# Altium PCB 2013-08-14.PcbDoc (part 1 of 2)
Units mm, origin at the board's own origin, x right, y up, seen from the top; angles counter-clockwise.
Board outline 30.96 x 91.67 mm, 2 copper layers (Top Layer, Bottom Layer); 88 components, 66 nets, 245 pads, 39 vias.
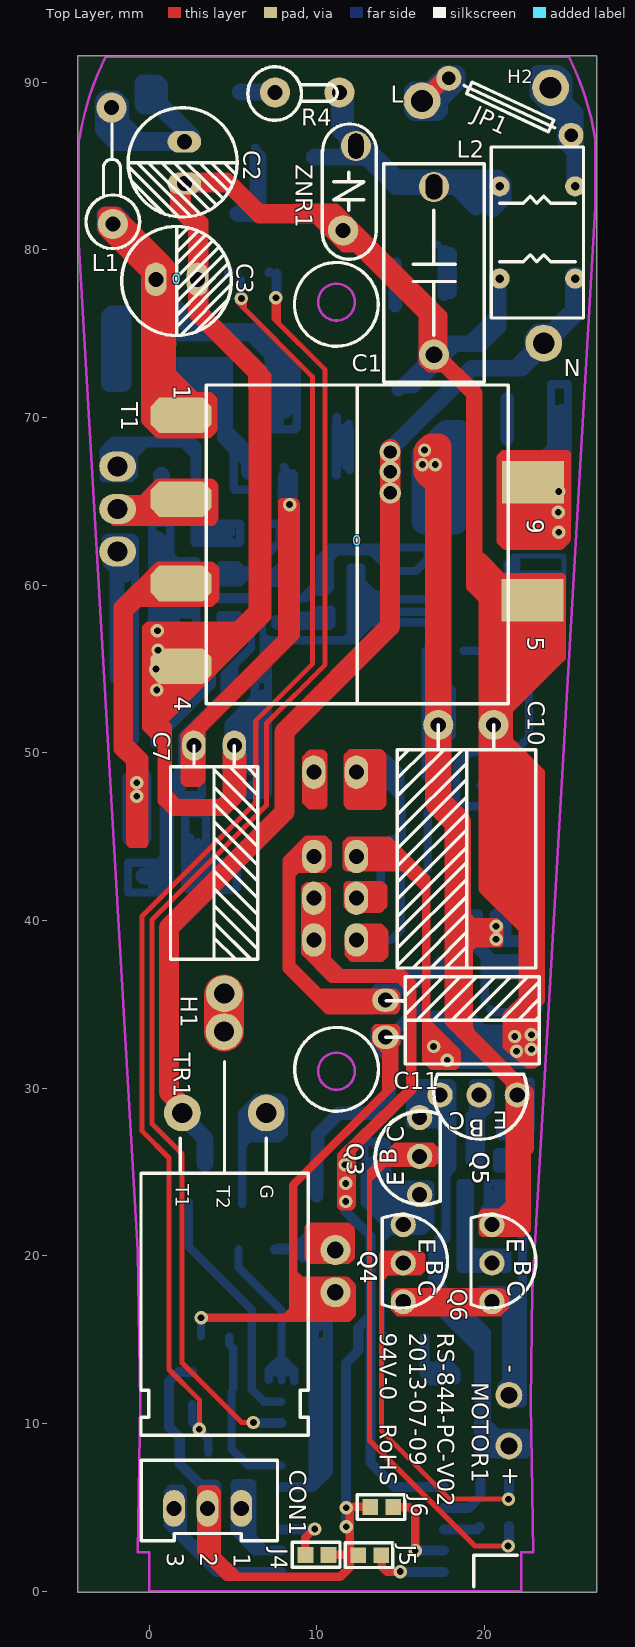
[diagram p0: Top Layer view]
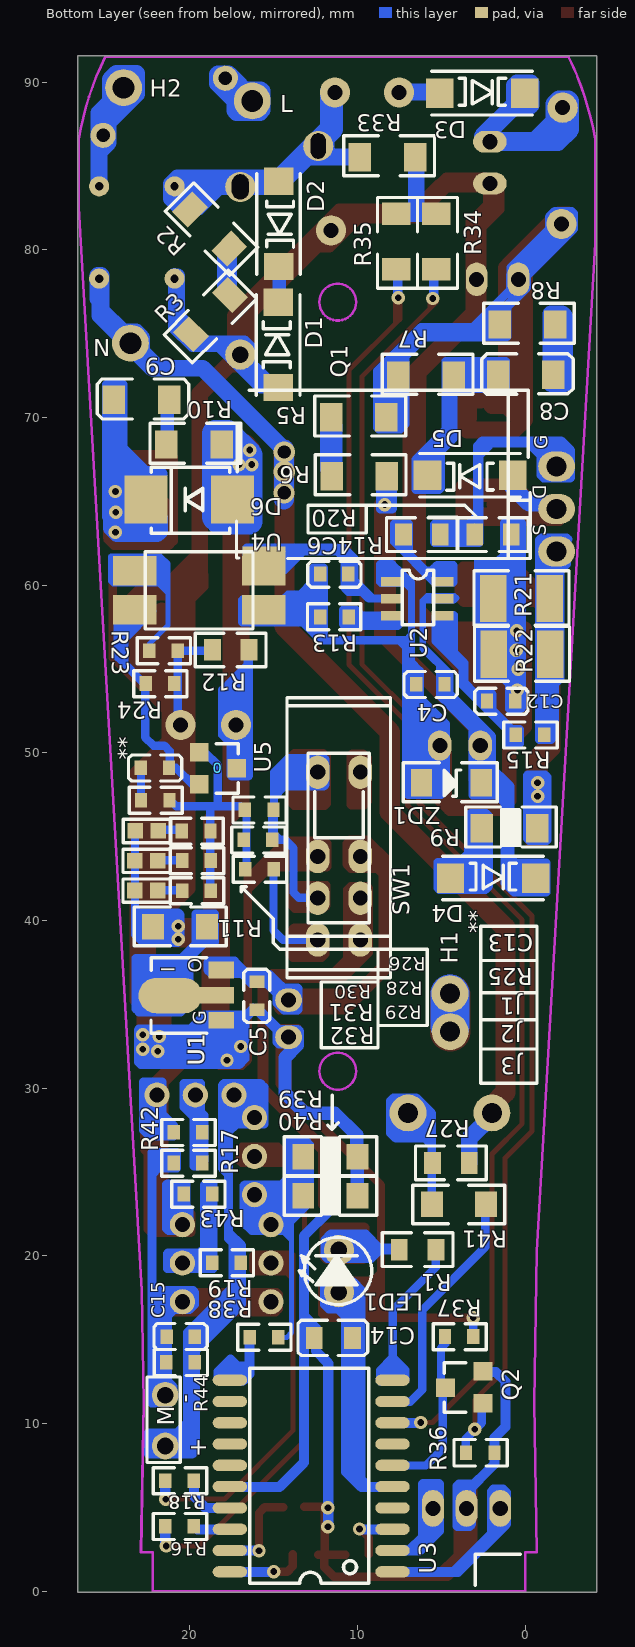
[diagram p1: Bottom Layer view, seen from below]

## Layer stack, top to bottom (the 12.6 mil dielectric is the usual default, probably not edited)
Top Layer: signal copper 0.0356
Dielectric: core 0.32, FR-4, Dk 4.8
Bottom Layer: signal copper 0.0356

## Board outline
-4.266,-0.075 26.694,-0.075 26.694,91.591 -4.266,91.591

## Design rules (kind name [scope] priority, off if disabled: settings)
Clearance [All] p1: gap=0.254
ComponentClearance [All] p1: gap=0.254 collisioncheckmode=3 verticalgap=0.254
PasteMaskExpansion PasteMaskExpansion_80 [HasPad('Free-201')] p1: expansion=-0.649
PasteMaskExpansion PasteMaskExpansion_78 [HasPad('Free-203')] p2: expansion=-0.623
PasteMaskExpansion [All] p3: expansion=-0.439
PolygonConnect [All] p1: connectstyle=Relief reliefconductorwidth=0.254 reliefentries=4 polygonreliefangle="90 Angle"
RoutingVias [All] p1: holewidth=0.711 width=1.27 viastyle="Through Hole" minholewidth=0.711 minwidth=1.27 maxholewidth=0.711 maxwidth=1.27
SolderMaskExpansion [(IsVia)] p1: expansion=-10
TestPointUsage [All] p1: valid=0 allowmultiple=FALSE
Testpoint [All] p1: side=15 testpointundercomponent=TRUE minsize=1.016 maxsize=2.54 preferedsize=1.524 minholesize=0 maxholesize=1.016 preferedholesize=0.813 testpointgrid=0.025 style=1023 order=0123456789
Width [All] p1: maxlimit=5 minlimit=2539.975 preferedwidth=2539.975 toplayer_minwidth=0 bottomlayer_minwidth=0
17 further rules are at their usual default settings.

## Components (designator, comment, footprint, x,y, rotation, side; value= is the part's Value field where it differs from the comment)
0 "Comment" 2.2uF/400V 1.646,78.247 r90 top
0 "Comment" TT1 12.405,62.655 r0 top locked
0 "Comment" TL431 18.324,49.085 r270 bottom
C4 "Comment" C0603 5.649,54.089 r180 bottom locked
C5 "" C0603 15.987,35.521 r270 bottom
C6 "Comment" C0603 11.389,60.667 r180 bottom
C7 "" c1 3.882,50.434 r0 top
C8 "Comment" C1206 -0.041,72.554 r0 top locked
C9 "Comment" C1206 22.881,71.058 r0 top
C10 "" C2 18.897,51.67 r180 top locked
C11 "" C3 14.107,34.15 r90 top
C12 "Comment" C0603 1.432,53.089 r180 bottom
C13 "Comment" C0603 22.083,49.11 r180 bottom
C14 "" C0805 11.44,15.1 r180 bottom
C15 "" C0603 20.533,15.176 r0 bottom
CON1 "" 3P 3.49,4.94 r0 top locked
D1 "Comment" D1 14.727,74.335 r270 top
D2 "Comment" D1 14.702,81.549 r90 top
D3 "Comment" D1 2.561,89.346 r0 top
D4 "Comment" D1 1.915,42.532 r0 top
D5 "Comment" D1 3.287,66.56 r180 top locked
D6 "Comment" D2 20.025,65.112 r0 bottom locked
J1 "Comment" R-J 22.565,45.351 r180 bottom
J2 "Comment" R-J 22.591,43.573 r180 bottom
J3 "Comment" R-J 22.591,41.795 r180 bottom
J4 "" RJJ 10.018,2.171 r0 top
J5 "" RJJ 13.167,2.146 r0 top
J6 "" RJJ 13.879,5.016 r0 top
JP1 "" FUSET 17.877,90.235 r335 top
L1 "Comment" L1 -2.164,81.549 r180 top
L2 "Comment" 共模电感 23.16,81.041 r270 top
LED1 "" LED 11.11,19.087 r180 bottom locked
Q3 "" Q1 16.139,25.945 r270 top locked
Q4 "" Q1 15.161,19.56 r90 top
Q5 "" Q1 19.66,29.591 r0 top
Q6 "" Q1 20.444,19.56 r90 top
R1 "" R0805#1 6.411,20.357 r0 bottom
R2 "Comment" R1206 18.817,81.244 r45 top
R3 "Comment" R1206 18.766,76.138 r135 top
R4 "" R2W 7.514,89.397 r0 top
R5 "Comment" R1206 9.921,70.014 r0 top
R6 "Comment" R1206 9.896,66.509 r0 top locked
R7 "Comment" R1206 5.903,72.504 r0 top locked
R8 "Comment" R1206 -0.142,75.552 r0 top
R9 "Comment" R1206 0.93,45.503 r0 top
R10 "Comment" R1206 19.757,68.391 r0 top
R11 "" R1 20.584,39.636 r0 bottom
R12 "Comment" R0805#2 17.561,56.146 r180 top locked
R13 "Comment" R0603 11.364,58.102 r0 bottom locked
R14 "Comment" R0805#2 6.157,63.029 r180 top
R15 "Comment" R0603 -0.295,51.082 r180 bottom
R16 "" R0603 20.61,3.873 r180 bottom
R17 "" R0603 20.102,25.539 r180 bottom
R18 "" R0603 20.61,6.591 r180 bottom
R19 "" R0603 17.816,19.595 r180 bottom
R20 "Comment" R0805#2 1.915,63.029 r180 top
R21 "Comment" R1210 0.213,59.21 r180 bottom
R22 "Comment" R1210 0.188,55.883 r180 bottom
R23 "Comment" R0603 21.575,56.095 r180 bottom locked
R24 "Comment" R0603 21.778,54.139 r180 bottom
R25 "Comment" R0603 22.057,47.18 r180 bottom
R26 "Comment" R0603 15.862,46.609 r180 bottom
R27 "" R0805#1 4.43,25.539 r0 bottom
R28 "Comment" R0603 15.936,44.818 r180 bottom
R29 "Comment" R0603 15.847,43.065 r180 bottom
R30 "Comment" R0603 19.621,45.339 r180 bottom locked
R31 "Comment" R0603 19.596,43.586 r180 bottom locked
R32 "Comment" R0603 19.596,41.783 r180 bottom locked
R33 "Comment" R1206 8.2,85.536 r0 top
R34 "Comment" R1206 5.304,80.507 r90 top
R35 "Comment" R1206 7.692,80.507 r90 top
R38 "" R0603 15.58,15.15 r180 bottom
R39 "" R1 11.618,25.92 r0 bottom
R40 "" R1 11.618,23.583 r0 bottom
R41 "" R1 3.947,23.075 r180 bottom
R42 "" R0603 20.102,27.368 r180 bottom
R43 "" R0603 19.517,23.685 r180 bottom
R44 "" R0603 20.559,13.652 r180 bottom
SW1 "" SW 11.1,43.847 r180 bottom locked
TR1 "" MSD 1.981,28.524 r0 top locked
U1 "" MSD1 19.644,35.547 r90 bottom
U2 "Comment" S08 6.436,59.194 r180 bottom locked
U3 "" SOP20 12.761,6.87 r90 bottom locked
U4 "" 光耦 19.441,59.702 r180 bottom
ZD1 "Comment" Z1 4.404,48.221 r180 bottom locked
ZNR1 "Comment" 10D 11.959,83.682 r0 top
? "Comment" 0.1UF/300V 16.988,78.755 r0 top
? "Comment" 2.2uF/400V 2.104,85.206 r0 top

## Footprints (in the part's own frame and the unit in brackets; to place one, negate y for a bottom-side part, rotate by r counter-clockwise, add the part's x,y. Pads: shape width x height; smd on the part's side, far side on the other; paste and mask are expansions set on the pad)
0.1UF/300V [mm]
  round 1.8 hole 1 slot 1.5 at 90 deg paste-0.53: 1(0,5.004)
  round 1.8 hole 1 paste-0.53: 2(0,-5.004)
  silkscreen extent -3,-6.63 3,6.38
2.2uF/400V [mm]
  oval 2x1.3 hole 0.9 paste-0.464: 1(0,1.245) 2(0,-1.244)
  silkscreen extent -3.35,-3.25 3.15,3.27
3P [mm]
  oval 1.3x2.2 hole 0.9 paste-0.45: 1(2.007,0) 2(0,0) 3(-2.007,0)
  silkscreen extent -3.96,-1.93 4.17,2.87
10D [mm]
  round 1.8 hole 0.9 slot 1.5 at 90 deg paste-0.467: 1(0.381,2.515)
  round 1.8 hole 0.9 paste-0.467: 2(-0.381,-2.515)
  silkscreen extent -1.63,-4.24 1.6,3.83
c1 [mm]
  oval 1.4x1.8 hole 0.9 paste-0.471: 1(-1.206,0) 2(1.207,0)
  silkscreen extent -2.6,-12.75 2.6,-1.27
C2 [mm]
  round 1.8 hole 0.9 paste-0.512: 1(-1.651,0) 2(1.651,0)
  silkscreen extent -4.17,1.47 4.09,14.5
C3 [mm]
  oval 1.4x1.6 hole 0.9 paste-0.471: 1(-1.105,-0.001) 2(1.105,0)
  silkscreen extent -2.71,-9.17 2.5,-0.99
C0603 [mm]
  rect 0.736x0.878 smd: 1(-0.838,0) 2(0.838,0)
  silkscreen extent -1.57,-0.79 1.6,0.76
C0805 [mil]
  rect 39.34x51 smd paste-25.5: 1(-45,0) 2(45,0)
  silkscreen extent -83,-41 81,42
C1206 [mil]
  rect 52.8x66.69 smd far side paste-33.35: 1(-65,0) 2(65,0)
D1 [mm]
  rect 1.631x1.755 smd far side paste-0.877: 1(2.54,0) 2(-2.54,0)
D2 [mm]
  rect 2.563x2.877 smd paste-1.438: 1(-2.578,0) 2(2.578,0)
  silkscreen extent -2.4,-1.93 2.27,2.01
FUSET [mm]
  round 1.5 hole 0.8 paste-0.316: 1(0,0) 2(8.052,0)
  silkscreen extent 1,-0.38 6.98,0.38
L1 [mm]
  round 1.8 hole 0.9 paste-0.469: 1(0,0) 2(0.076,-6.934)
  silkscreen extent -1.6,-5.97 1.6,1.47
LED [mm]
  round 1.8 hole 1 paste-0.47: A(0,-1.257) K(0,1.257)
  silkscreen extent -2.36,-1.99 1.95,2.02
MSD [mm]
  round 2.2 hole 1.2 paste-0.623: G(5.004,0) T1(0,0)
  round 2.2 hole 1.2: T2(2.489,4.851)
  silkscreen extent -2.46,-19.23 7.52,3.05
MSD1 [mil]
  rect 39.12x59.51 smd paste-29.75: G(-59,-60) I(0,-60) I(0,-37) O(59,-60)
  oval 83.28x148.96 smd paste-74.48: I(-1,60)
  silkscreen extent -90,-25 88,105
Q1 [mm]
  round 1.5 hole 0.9 paste-0.432: B(0.013,0) C(-2.299,0) E(2.299,0)
  silkscreen extent -2.67,-2.64 2.9,1.24
R1 [mm]
  rect 1.305x1.52 smd paste-0.76: 1(-1.612,0) 2(1.613,0)
  silkscreen extent -2.76,-1.17 2.73,1.14
R2W [mm]
  round 1.8 hole 0.9 paste-0.469: 1(0,0) 2(3.835,0)
  silkscreen extent -1.62,-1.67 3.71,1.52
R0603 [mm]
  rect 0.736x0.878 smd: 1(0.851,0) 2(-0.851,0)
  silkscreen extent -1.56,-0.79 1.61,0.76
R0805#1 [mm]
  rect 0.999x1.295 smd paste-0.648: 1(-1.092,0) 2(1.092,0)
  silkscreen extent -2.11,-1.02 2.11,0.99
R0805#2 [mm]
  rect 0.999x1.295 smd far side paste-0.648: 1(-1.092,0) 2(1.092,0)
R1206 [mil]
  rect 52.8x66.69 smd far side paste-33.35: 1(-65,0) 2(65,0)
  Bottom Layer lines w19.68: -73.91,22.54 -70.95,19.58
R1210 [mm]
  rect 1.567x2.807 smd paste-1.403: 1(-1.689,0) 2(1.689,0)
  silkscreen extent -2.83,-1.6 2.83,1.65
R-J [mm]
  rect 0.939x0.939 smd paste-0.47: 1(-0.686,0) 2(0.686,0)
  silkscreen extent -1.4,-0.71 1.42,0.69
RJJ [mil]
  rect 36.97x36.97 smd paste-18.48: 1(-27,0) 2(27,0)
  silkscreen extent -58,-29 54,29
S08 [mm]
  rect 1.301x0.565 smd paste-0.65: 1(-1.511,1.004) 2(-1.511,0.012) 3(-1.511,-1.004) 4(1.512,-1.004) 5(1.512,0.012) 6(1.512,1.004)
  silkscreen extent -0.9,-1.56 0.98,1.69
SOP20 [mil]
  oval 26.31x80.65 smd paste-40.33: 1(-225,-191) 2(-175,-191) 3(-125,-191) 4(-75,-191) 5(-25,-191) 6(25,-191) 7(75,-191) 8(125,-191) 9(175,-191) 10(225,-191) 11(225,191) 12(175,191) 13(125,191) 14(75,191) 15(25,191) 16(-25,191) 17(-75,191) 18(-125,191) 19(-175,191) 20(-225,191)
  silkscreen extent -252,-135 253,144
SW [mm]
  oval 1.4x2 hole 0.9 paste-0.448: 1(1.27,5.004) 2(1.27,-0.025) 3(1.27,-2.515) 4(1.27,-5.004) 5(-1.27,-5.004) 6(-1.27,-2.514) 7(-1.27,-0.025) 8(-1.27,5.004)
  silkscreen extent -3.1,-7.26 3.07,9.45
TL431 [mil]
  rect 43.66x43.66 smd paste-21.85: 1(-37.5,-44) 2(37.5,-44) 3(0.49,44)
  silkscreen extent -58,-4 58,47
TT1 [mm]
  oct 3.655x2.126 smd paste-1.827: 1(-10.503,7.48) 3(-10.503,2.476) 4(-10.503,-7.48) 5(-10.503,-2.553)
  rect 3.699x2.537 smd paste-1.85: 7(10.452,-3.543) 9(10.503,3.492)
  silkscreen extent -9,-9.72 9,9.28
Z1 [mil]
  rect 50.28x64.72 smd paste-32.36: 1(-70,0) 2(70,0)
  silkscreen extent -113,-45 108,47
光耦 [mm]
  rect 2.585x1.748 smd paste-1.293: 1(-3.848,1.169) 2(-3.848,-1.168) 3(3.848,-1.168) 4(3.848,1.169)
  silkscreen extent -3.21,-2.31 3.21,2.29
共模电感 [mm]
  round 1.2 hole 0.5: 1(-2.75,2.25) 2(-2.75,-2.25) 3(2.75,-2.25) 4(2.75,2.25)
  silkscreen extent -5.1,-2.75 5.1,2.75

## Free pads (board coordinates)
  round 2.2 hole 1.2: 1(4.481,35.641)
  round 1.6 hole 1 paste-0.475: 1(21.463,8.661) 2(21.463,11.684)
  rect 2.585x1.748 smd far side paste-1.293: 4(15.57,61.443)
  rect 1.631x1.755 smd far side paste-0.877: 32(5.817,66.573) 33(0.737,66.573)
  rect 0.999x1.295 smd far side paste-0.648: 50(12.573,15.088) 51(10.287,15.088)
  rect 1.109x1.109 smd far side paste-0.555: 89(4.75,12.141) 90(2.515,13.106) 91(2.515,11.201)
  rect 0.736x0.878 smd far side: 138(4.775,15.189) 139(3.099,15.189) 140(3.531,8.255) 141(1.829,8.255)
  rect 0.939x0.939 smd paste-0.47: 174(10.693,2.159) 175(9.322,2.159)
  round 2.2 hole 1.3: 201(16.277,88.889) 201(23.541,74.437) 201(23.948,89.677)
  oval 2.2x1.8 hole 1.2 paste-0.588: 250(-1.88,62.008) 251(-1.88,64.548) 252(-1.88,67.088)

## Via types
v1: diameter 0.8, hole 0.4, Top Layer to Bottom Layer, 36 vias
v2: diameter 1.27, hole 0.8, Top Layer to Bottom Layer, 3 vias

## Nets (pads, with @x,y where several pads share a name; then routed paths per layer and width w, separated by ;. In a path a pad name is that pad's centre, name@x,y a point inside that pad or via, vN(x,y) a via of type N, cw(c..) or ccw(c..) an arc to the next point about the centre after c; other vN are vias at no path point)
H2: JP1.2 L2.1 pad.201@23.948,89.677 | length 20.3
  Bottom Layer w1: pad.201@23.186,89.499 23.186,89.296 24.684,87.797 ; pad.201@23.871,89.702 25.41,88.163 L2.1@25.41,83.791 ; 24.938,88.33 24.74,88.529 24.74,90.18 24.379,90.54 23.211,90.54 23.186,90.515 23.186,89.321 23.516,88.991 23.744,88.991 24.862,87.873 24.862,86.4 25.41,85.852 L2.1@25.41,83.835
L: ?.1@16.988,83.759 D2.1 L2.2 R2.2 R4.2 R33.2 ZNR1.1 | length 41.3
  Bottom Layer w0.3: D2.1@14.984,83.756 L2.2@20.821,83.756
  Bottom Layer w1: R33.2@9.851,85.536 ZNR1.1@12.899,85.536 ; 11.222,85.536 11.502,85.536 ZNR1.1@11.806,85.841 ; R4.2@11.349,89.397 11.349,87.162 14.727,83.784 L2.2@20.95,83.784 ; R4.2@11.73,89.448 11.73,87.314 14.753,84.292 20.747,84.292 21.103,83.936 21.103,83.073 R2.2@20.468,82.438 ; ZNR1.1@11.857,86.654 11.857,85.892 ZNR1.1@11.908,85.841 ; 18.385,83.682 R2.2@19.503,82.565 ; 19.452,83.2 19.706,83.454 ; R2.2@20.011,82.996 20.442,83.428 L2.2@20.874,83.428
L-IN: JP1.1 pad.201@16.277,88.889 | length 11.5
  Top Layer w1: pad.201@16.277,88.889 JP1.1@17.623,90.235
  Bottom Layer w1: pad.201@16.251,88.788 16.251,89.067 17.674,90.489 18.334,90.489 18.36,90.464 18.36,89.931 17.318,88.889 17.318,88.305 17.217,88.203 15.82,88.203 15.693,88.33 15.693,89.473 15.769,89.55 pad.201@16.861,89.55
N: 0.2@2.891,78.247 0.4 0.7 ?.2 C4.1 C5.2 C6.1 C7.2 C10.1 C11.1 C12.2 C14.2 D1.1 L2.3 LED1.A pad.51 pad.139 R3.1 R12.1 R13.1 R20.2 R21.1 R22.1 R23.1 R24.1 R39.1 R40.1 SW1.7 U1.G U2.1 U3.5 U4.3 ZD1.1 ZNR1.2 | length 806.1
  Top Layer w0.5: 1.128,51.595 1.128,47.548 1.668,47.008 4.245,47.008 4.624,47.387 4.624,49.982 4.732,50.09 5.383,50.09 5.561,49.912 5.561,47.518 4.518,46.475 1.412,46.475 0.761,47.126 0.761,50.563 -0.164,51.488 -0.164,57.474 -0.046,57.592 5.205,57.592 6.165,58.552 6.165,71.933 ; ?.2@1.494,84.114 1.494,82.387 2.561,81.32 2.561,76.138 6.142,72.557 6.142,71.77 ; 2.256,82.742 3.297,81.701 3.297,76.265 7.054,72.509 7.054,58.102 6.828,57.876 ; v1@3.238,16.314 11.877,16.314 12.097,16.534 12.097,18.193 11.759,18.531 9.05,18.531 8.595,18.986 ; 8.151,16.314 8.595,16.758 8.595,24.218 14.641,30.263 C11.1@14.641,32.81 ; 14.148,29.746 C11.1@14.148,32.48 ; 14.321,31.841 14.321,32.019 13.559,32.781 13.559,33.568 14.702,33.568 14.753,33.517 14.753,32.73 14.346,32.323 14.346,31.663 ; C11.1@14.367,33.064 C11.1@14.61,32.821 ; 14.437,30.06 C11.1@14.437,32.88 ; 14.437,30.88 14.539,30.981 ; 16.542,33.944 18.358,32.128 18.358,31.474 18.227,31.343 ; 16.542,41.858 15.22,43.18 11.83,43.18 11.795,43.215 11.795,44.602 11.949,44.756 14.296,44.756 16.542,42.51 ; 16.542,42.532 16.542,31.686 16.885,31.343 18.195,31.343 ; 19.147,60.619 19.147,59.899 19.902,59.144 19.902,41.855 22.272,39.485 22.272,35.926 ; 19.842,61.705 21.075,60.472 24.607,60.472 24.607,55.683 21.442,52.518 21.442,50.766 23.351,48.857 23.351,35.215 22.942,34.806 ; 21.585,34.381 21.585,32.679 21.636,32.628 ; v1@21.89,32.273 21.89,34.736 ; 22.449,35.473 21.331,34.355 21.331,32.508 22.582,31.435 22.819,31.435 22.942,31.432 22.942,36.806
  Top Layer w0.8: ?.2@2.027,83.86 5.075,83.86 6.599,82.336 10.587,82.336 16.937,75.986 16.937,73.802 ?.2@16.988,73.751 ; ?.2@2.104,83.962 2.104,82.59 2.916,81.777 2.916,76.519 6.65,72.786 6.65,71.795 ; ?.2@2.383,84.216 4.669,84.216 5.863,83.022 ; ?.2@2.459,83.835 4.694,83.835 6.549,81.98 9.952,81.98 11.679,80.253 12.365,80.253 16.48,76.138 16.48,73.37 16.759,73.09 17.648,73.09 ; 8.784,82.361 11.095,82.361 17.394,76.062 ?.2@17.394,73.548
  Top Layer w1: 0.216,51.559 0.216,56.941 0.428,57.153 4.979,57.153 0.5,52.674 0.5,53.539 3.451,56.49 2.053,56.49 0.168,54.605 0.168,55.612 1.093,56.537 ; 0.642,51.15 0.642,52.045 6.722,58.125 6.722,71.862 ; 1.063,47.275 1.608,46.73 4.435,46.73 5.11,47.405 C7.2@5.11,49.604 ; 9.027,18.258 9.027,16.794 9.039,16.806 11.457,16.806 11.51,16.859 11.51,17.992 11.474,17.956 9.407,17.956 ; 9.43,17.428 LED1.A@10.569,17.428 ; SW1.7@12.257,44.306 14.26,44.306 14.936,43.63 SW1.7@12.612,43.63 ; ?.2@17.064,73.776 19.401,71.439 19.401,60.39 ; ?.2@17.181,73.748 ?.2@17.206,73.748 ; 17.235,31.882 16.844,32.273 16.844,32.973 17.839,31.978 v1@17.839,31.799 ; 19.487,60.424 20.34,59.571 20.34,42.007 22.711,39.636 22.711,39.494 ; 19.57,61.337 21.312,59.595 22.876,59.595 24.085,58.386 24.085,55.825 21.028,52.768 21.028,50.634 22.77,48.892 22.77,35.607 22.533,35.37 ; 20.992,59.547 20.992,42.421 22.308,41.105 22.308,48.975 21.62,49.663 21.62,41.865 ; 0.7@21.668,58.481 21.668,53.859 23.54,55.731 23.54,57.983 23.184,57.627 22.189,57.627 22.379,57.437 22.379,54.83 23.114,55.565 23.114,57.818 ; v1@22.533,32.048 22.533,37.37
  Bottom Layer w0.4: 6.815,59.779 7.478,60.442 U2.1@8.027,60.442 ; 6.858,54.788 6.772,54.874 6.772,60.178 7.429,60.835 8.696,60.835 ; 7.127,60.204 7.17,60.204 7.521,60.555 8.566,60.555 ; 7.133,60.097 8.61,60.097 8.696,60.183 8.696,61.043 ; 7.747,60.879 7.844,60.879
  Bottom Layer w0.5: v1@0.185,53.678 v1@0.714,53.678 ; 0.811,54.993 1.35,55.532 2.741,55.532 2.805,55.596 ; 0.961,54.218 0.961,54.98 ; 1.062,60.873 2.612,60.873 ; 1.088,61.508 1.469,61.127 2.612,61.127 ; 1.545,57.596 2.688,57.596 ; 1.621,57.342 2.637,57.342 ; pad.139@3.099,15.189 v1@3.099,16.169 ; 5.397,47.992 5.397,51.662 5.882,52.147 5.882,49.098 6.109,48.871 6.109,52.643 5.042,51.576 5.042,47.932 5.203,47.771 5.818,47.771 6.405,48.358 6.405,53.182 6.761,53.538 ZD1.1@6.761,47.717 ; C4.1@6.691,54.4 6.691,55.052 ; 6.838,60.066 6.838,60.293 ; 6.96,47.501 5.015,47.501 4.74,47.776 4.74,51.743 6.292,53.295 6.292,54.895 6.831,55.434 6.831,56.933 7.057,56.707 12.172,56.707 13.265,57.8 U4.3@16.785,57.8 ; 6.982,47.501 7.095,47.614 7.095,56.303 7.499,56.707 ; 7.405,60.724 7.928,61.246 8.641,61.246 8.641,60.781 ; 11.724,56.739 12.021,57.036 12.021,61.035 12.646,61.035 12.646,60.167 12.985,59.828 ; 12.463,57.289 C6.1@12.463,60.398 ; 12.609,58.232 12.9,58.523 13.234,58.523 ; 12.645,59.832 12.924,59.552 12.924,59.273 ; 12.646,60.211 13.432,59.425 14.143,59.425 14.397,59.171 16.81,59.171 16.861,59.12 U4.3@16.861,57.8 ; 12.652,58.771 14.258,58.771 ; 12.695,59.288 14.253,59.288 ; 12.706,58.97 U4.3@14.42,58.97 ; 12.733,57.268 12.733,57.99 13.158,58.415 U4.3@16.759,58.415 ; 12.942,59.369 13.903,59.369 ; 12.949,57.825 13.178,58.054 U4.3@14.753,58.054 ; C11.1@13.559,33.339 C11.1@13.737,33.517 ; C11.1@13.584,33.517 14.677,33.517 15.843,34.683 C5.2@15.987,34.683 ; C11.1@14.296,32.628 14.702,32.628 14.804,32.73 C11.1@14.804,33.339 ; 14.854,33.492 15.921,34.559 C5.2@15.972,34.559 ; D1.1@14.88,71.744 D1.1@14.982,71.744 ; C5.2@16.061,34.774 16.699,34.136 16.699,31.742 17.044,31.397 22.919,31.397 23.07,31.548 23.07,33.488 ; C5.2@16.213,34.8 16.641,34.372 19.146,34.372 19.976,33.542 23.048,33.542 ; R12.1@18.758,56.103 20.612,56.103 20.709,56.006 C10.1@20.709,51.551 ; 0.185,52.682 0.249,52.618 0.935,52.618 0.961,52.643 0.961,54.117 1.291,54.447 2.764,54.447 2.805,54.488 2.805,61.439 1.608,61.439 1.263,61.784 1.263,63.725 0.185,63.725 0.185,52.682
  Bottom Layer w0.6: U3.5@7.899,6.223 9.769,6.223 10.668,7.122 10.668,16.387 11.148,16.867 11.698,16.867 11.924,17.093 11.924,18.311 ; 9.387,6.223 10.34,7.176 pad.51@10.34,14.862 ; 9.822,6.658 9.822,17.966 10.253,18.397 11.827,18.397 ; 10.194,15.806 10.194,17.552 10.593,17.951 LED1.A@10.593,18.01 ; 10.194,16.597 11.331,17.734 LED1.A@11.331,18.133 ; LED1.A@10.453,17.379 LED1.A@10.453,17.605
  Bottom Layer w0.8: R40.1@10.006,23.583 R39.1@10.006,25.882 ; R39.1@10.054,25.872 10.054,27.218 11.349,28.513 13.127,28.513 14.321,29.707 14.321,31.815 13.584,32.552 C11.1@13.584,33.361 ; C11.1@13.828,33.057 C11.1@14.183,33.083 ; D1.1@14.854,71.643 17.521,74.31 19.833,74.31 20.91,75.387 20.91,78.515 20.895,78.501 20.722,78.501 20.696,78.475 20.696,76.062 19.122,74.487 16.759,74.487 16.404,74.132 ?.2@16.404,73.319 ; D1.1@15.286,71.846 15.769,71.846 18.309,74.386 18.334,74.386
  Bottom Layer w1: v1@0.58,53.532 0.498,53.614 0.498,62.721 0.649,62.57 0.649,59.358 1.489,58.518 R21.1@2.504,58.518 ; 0.628,55.5 1.317,56.189 R21.1@1.317,58.776 ; C11.1@14.11,33.009 C11.1@14.346,33.009 ; 17.238,33.488 17.238,32.109 17.573,31.774 22.37,31.774 22.499,31.903 22.499,32.324 22.467,32.356 18.413,32.356 17.874,32.895 ; 17.239,33.844 18.909,33.844 19.653,33.1 v1@22.736,33.1 ; 17.874,32.443 17.874,33.057 17.906,33.025 19.2,33.025
  other v1: 3.099,16.307 17.78,31.674 21.916,32.196 22.805,32.323 16.967,32.487 21.814,33.085 22.805,33.187 0.457,53.753 0.406,54.998 0.533,56.115 0.498,57.28
N-IN: L2.4 pad.201@23.541,74.437 R27.1 TR1.T1 | length 79.7
  Top Layer w1: TR1.T1@1.941,28.46 TR1.T1@1.941,28.993 ; v2@14.361,67.949 v2@14.372,67.96
  Top Layer w1.2: TR1.T1@1.941,28.994 1.18,29.754 1.18,39.579 8.073,46.471 8.073,51.255 14.361,57.543 v2@14.361,67.949 ; v2@14.397,65.674 v2@14.397,68.112
  Bottom Layer w1: TR1.T1@1.941,28.384 3.338,26.987 R27.1@3.338,25.539 ; v2@14.372,68.087 19.223,72.938 22.22,72.938 25.37,76.088 L2.4@25.37,78.374 ; 22.017,73.065 22.881,73.929 22.881,74.767 23.211,75.097 23.998,75.097 25.294,76.392 25.294,78.475 25.497,78.475 25.472,78.45 25.472,77.098 25.37,76.996
  Bottom Layer w1.2: v2@14.372,65.126 v2@14.372,68.087
  other v2: 14.376,65.507 14.372,66.777 14.372,67.945
NewNet1: 
NewNet2: J4.1 pad.175 U3.3 | length 3.5
  Top Layer w0.5: pad.175@9.318,2.187 9.318,3.195 v1@9.839,3.716
  Bottom Layer w0.6: U3.3@7.899,3.683 v1@9.662,3.683
  other v1: 9.881,3.708
NewNet3: J5.2 U3.20 | length 4.4
  Top Layer w0.5: J5.2@13.869,2.211 13.869,1.476 14.189,1.156 v1@14.936,1.156
  Bottom Layer w0.6: v1@15.106,1.143 U3.20@17.602,1.143
  other v1: 14.986,1.168
NewNet4: J6.2 U3.19 | length 5.5
  Top Layer w0.5: J6.2@14.42,5.008 15.528,5.008 15.875,4.661 v1(15.875,2.413)
  Bottom Layer w0.6: v1@15.966,2.413 U3.19@17.602,2.413
NewNet5: C14.1 CON1.2 J4.2 J5.1 J6.1 pad.50 pad.90 pad.141 pad.174 SW1.3 SW1.4 U3.16 | length 154.1
  Top Layer w0.5: 3.629,2.365 3.629,5.191 3.481,5.339 3.481,2.181 4.601,1.061 4.832,1.061 ; 5.152,1.008 4.032,2.128 4.032,5.938 3.89,6.08 3.125,6.08 3.096,6.051 3.096,2.37 4.607,0.859 11.403,0.859 11.973,1.429 11.973,2.092 ; 10.526,37.788 11.748,36.566 12.031,36.849 ; 10.551,36.849 15.079,36.849 15.566,36.362 15.566,30.037 ; 10.598,37.301 10.598,41.853 10.397,42.054 9.443,42.054 9.318,41.929 9.318,38.082 10.881,36.518 14.939,36.518 15.684,35.773 ; 10.678,37.204 10.831,37.052 10.907,37.052 ; pad.174@10.716,2.169 J5.1@12.334,2.169 ; v1@11.831,23.118 11.831,25.918 ; 11.961,2.371 11.961,4.926 11.858,5.029 J6.1@13.183,5.029 ; 14.802,36.849 15.706,35.944 ; 15.108,36.845 15.706,36.247 15.706,29.903 12.103,26.3 12.103,23.047 12.019,22.963 11.476,22.963 11.451,22.988 11.451,25.973 15.581,30.002
  Top Layer w1: SW1.4@9.78,38.093 SW1.3@9.78,41.637 ; 10.165,37.781 SW1.3@10.165,41.432
  Bottom Layer w0.6: pad.90@2.546,13.073 1.749,13.073 1.177,12.501 1.177,9.807 1.829,9.155 1.829,7.581 3.538,5.872 CON1.2@3.538,5.376 ; v1(11.688,25.431) 11.688,22.697 13.201,21.184 13.201,7.662 14.64,6.223 U3.16@17.602,6.223 ; v1@11.741,3.889 11.741,13.59 12.474,14.323 12.474,15.698 13.201,16.425 ; CON1.2@3.215,3.996 3.312,3.899 4.023,3.899 4.023,6.271 3.948,6.346 3.215,6.346 CON1.2@3.215,3.996
  other v1: 11.76,3.835 11.76,4.978 11.724,23.242 11.724,24.32
NewNet6: 0.5 R9.1 | length 87.2
  Top Layer w0.5: -1.118,44.632 -1.118,49.432 -1.87,50.184 -1.87,58.748 0.559,61.177 3.711,61.177 3.949,60.939 3.949,59.222 3.67,58.943 -0.614,58.943 -1.224,58.333 -1.224,50.635 -0.271,49.682 -0.271,44.578 -1.106,44.578
  Top Layer w1: -0.768,44.851 -0.768,49.651 -1.574,50.457 -1.574,58.505 0.571,60.65 3.332,60.65 3.463,60.519 3.463,59.453 3.332,59.322 -0.495,59.322
  Bottom Layer w0.5: R9.1@-0.968,45.668 -0.968,48.385 -0.806,48.547 -0.806,46.219 -0.407,45.82 -0.407,48.45 ; -0.192,48.698 -1.183,48.698 -1.323,48.558 -1.323,44.795 -1.291,44.763 -0.235,44.763 -0.116,44.882 -0.116,48.66 -0.154,48.698
  other v1: -0.741,47.411 -0.741,48.224
NewNet7: D4.1 R9.2 | length 28.7
  Bottom Layer w0.5: R9.2@2.471,44.947 2.471,42.381 2.622,42.23 3.592,42.23 2.924,42.898 2.924,44.677 2.837,44.59 2.837,42.402 ; 2.934,41.831 5.112,41.831 5.22,41.939 5.22,43.491 3.894,43.491 3.398,43.987 3.398,46.251 3.247,46.402 2.331,46.402 2.158,46.229 2.158,42.036 2.363,41.831 D4.1@5.079,41.831 ; 3.118,43.793 3.71,43.201 3.71,42.543 3.204,43.049 3.204,44.052
NewNet8: C4.2 C7.1 D4.2 R6.1 U2.5 ZD1.2 | length 118.2
  Top Layer w0.5: 7.943,63.109 8.073,63.239 ; 8.614,56.87 8.614,56.893 8.758,57.038 8.758,64.861 8.657,64.962 7.946,64.962 7.943,64.96 7.943,56.857 2.124,51.038 2.124,48.318 2.237,48.205 2.923,48.205 3.113,48.395 3.113,51.369 8.69,56.946
  Top Layer w1: 2.621,48.62 C7.1@2.621,51.097 ; 8.2,62.676 8.2,63.112 ; 8.287,56.952 8.287,62.712 ; 8.454,63.21 v1@8.454,64.658
  Bottom Layer w0.4: 5.958,59.1 4.259,59.1 4.125,59.234 4.233,59.342 5.839,59.342 6.109,59.072 6.109,56.224
  Bottom Layer w0.5: 1.382,47.361 1.716,47.695 1.716,48.342 1.22,47.846 1.22,47.642 1.328,47.534 1.328,47.296 1.986,47.954 1.986,48.849 ; 1.977,48.986 1.977,50.992 4.519,53.535 4.519,54.701 6.028,56.21 ; 2.205,49.338 0.875,48.008 0.875,43.76 0.553,43.438 -1.259,43.438 -1.259,41.67 0.66,41.67 1.231,42.241 1.231,47.027 1.684,47.48 3.139,47.48 3.139,51.683 ; C7.1@2.406,51.177 2.406,49.054 2.719,48.741 2.719,51.609 4.799,53.689 C4.2@4.799,53.872 ; 3.139,51.469 5.075,53.405 5.075,55.107 ; 5.015,53.559 5.015,55.004 ; R6.1@7.895,65.775 7.895,64.556 7.92,64.531 8.022,64.531 ; 7.996,64.531 v1@8.628,64.531 ; v1@8.216,65.039 R6.1@8.216,65.896 ; v1@8.328,64.732 8.577,64.732 v1@8.642,64.797 ; R6.1@8.572,66.677 8.642,66.607 v1@8.642,64.531
  Bottom Layer w1: D4.2@-0.31,42.661 0.142,42.661 0.735,43.254 0.735,42.488 0.391,42.144 ; v1@8.189,64.871 R6.1@8.189,66.484
  other v1: 8.377,64.81
NewNet10: 
NewNet11: Q3.B R16.2 | length 45.3
  Top Layer w0.3: 13.146,24.516 14.088,25.458 16.957,25.458 17.122,25.623 17.122,26.389 16.909,26.602 14.698,26.602 13.146,25.05 13.146,8.99 19.444,2.692 v1(21.412,2.692)
  Top Layer w0.5: 14.586,26.005 14.377,26.005 13.322,24.95 13.322,25.045 14.107,25.83 15.249,25.83
  Top Layer w1: Q3.B@16.631,26.193 15.007,26.193 15.256,25.944 Q3.B@16.678,25.944
  Bottom Layer w0.6: v1@21.463,2.826 R16.2@21.463,3.886
NewNet12: Q4.B R18.2 | length 30.7
  Top Layer w0.3: 13.893,18.655 14.231,18.993 16.156,18.993 16.322,19.159 16.322,20.018 16.174,20.166 13.945,20.166 13.851,20.072 13.851,9.571 17.936,5.486 v1(21.438,5.486)
  Top Layer w1: 14.254,19.378 15.712,19.378 15.813,19.479 15.813,19.674 15.765,19.722 14.325,19.722 14.515,19.532 Q4.B@14.77,19.532
  Bottom Layer w0.6: v1@21.463,5.512 R18.2@21.463,6.579
NewNet13: R11.1 U1.I | length 32.7
  Bottom Layer w0.5: R11.1@19.34,38.925 19.594,38.671 19.594,38.569 ; U1.I@20.03,35.148 20.03,37.767 19.092,38.705 18.499,38.705 18.499,40.398 19.653,40.398 19.653,38.597 20.482,37.768 23.231,37.768 23.231,34.727 23.038,34.534 20.536,34.534 U1.I@20.353,34.717 ; 20.731,36.69 22.402,36.69 22.499,36.787 22.499,36.592 22.779,36.312 22.779,37.11 22.747,37.142 20.753,37.142 20.623,37.272 20.623,36.928 20.353,36.658 20.353,37.51 20.3,37.563 22.843,37.563 23.059,37.347 23.059,34.932 22.823,34.696 U1.I@22.477,34.696
NewNet14: C5.1 C11.2 SW1.2 U1.O | length 69.1
  Top Layer w0.5: 8.447,42.712 9.027,43.292 ; 8.672,43.148 8.494,42.97 8.494,37.354 10.116,35.731 10.094,35.579 ; 8.678,43.097 10.408,43.097 10.657,43.346 10.657,44.596 10.444,44.809 9.395,44.809 8.192,43.606 8.192,37.125 10.399,34.918 ; 9.684,35.63 13.778,35.63 C11.2@14.509,35.102 ; 10.124,35.702 14.626,35.702 14.753,35.524 14.753,34.813 14.677,34.686 13.153,34.686 ; 10.294,35.023 10.657,34.66 14.651,34.66 ; 10.5,34.969 13.269,34.969 13.32,35.02 ; 10.5,35.325 C11.2@13.396,35.325
  Top Layer w1: SW1.2@9.792,44.092 9.247,44.092 8.607,43.452 SW1.2@10.076,43.452
  Bottom Layer w0.5: C11.2@13.98,35.115 13.98,35.547 15.221,36.787 16.516,36.787 17.324,37.595 18.866,37.595 ; C11.2@14.321,35.371 14.321,35.473 15.464,36.616 C5.1@15.769,36.616 ; 14.421,35.987 13.565,35.987 13.534,35.956 13.534,34.686 13.559,34.66 14.397,34.66 14.804,35.067 14.804,35.625 15.415,36.237 16.333,36.237 16.926,36.83 18.725,36.83 18.931,37.036 18.931,37.52 ; 17.325,37.164 U1.O@18.521,37.164
NewNet15: Q3.E Q4.E R38.1 R39.2 R40.2 | length 41.7
  Bottom Layer w0.3: 13.929,20.933 14.77,21.774 Q4.E@14.77,21.949 ; 13.929,22.37 13.929,15.428 14.215,15.142 R38.1@14.684,15.142
  Bottom Layer w0.5: 14.102,21.367 14.102,21.937 12.851,23.188 12.851,26.643 13.013,26.805 14.155,26.805 14.155,24.639 14.538,24.256 16.721,24.256 16.78,24.197 16.78,21.971 16.3,21.491 14.193,21.491
  Bottom Layer w1: R39.2@13.336,25.458 13.336,23.323 14.661,21.998 15.956,21.998 16.268,22.31 16.268,23.614 16.073,23.809 14.252,23.809 13.735,24.326 13.735,24.682 ; R39.2@13.828,26.58 13.955,26.453 13.955,24.726 ; 14.026,23.701 14.112,23.701 15.158,22.655 15.762,22.655 ; 14.296,23.022 15.373,23.022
